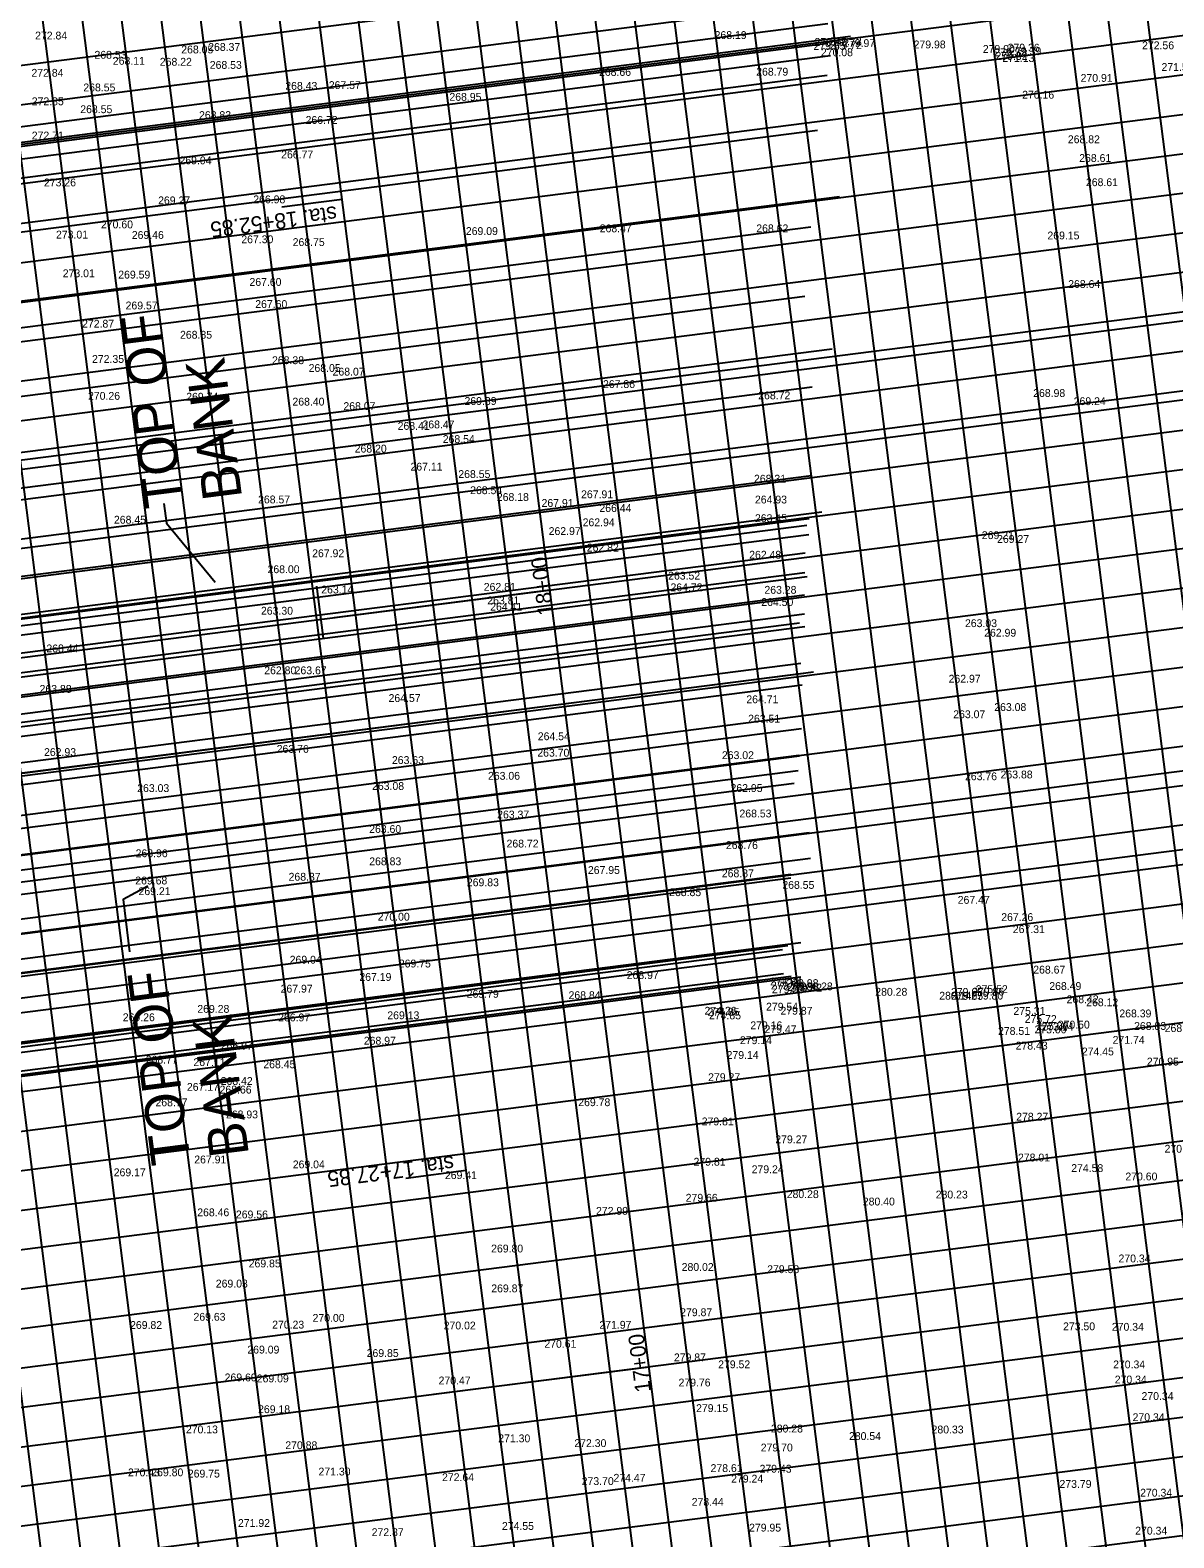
# Model space of a CAD drawing. Extents: x 2166991 to 2168450, y 842134 to 844444.
# Drawn here: x 2167986.8 to 2168132.8, y 843313.8 to 843506.3 of the extents above; entities that cross this region are included whole.
import ezdxf

# ---------------------------------------------------------------- set-up
doc = ezdxf.new("R2010")
doc.units = 0
for name, color, linetype in [('Exist Plan Preparation Drainage Notes Label', 7, 'Continuous'), ('Prop Boundary Buffer Zone 1', 7, 'Continuous'), ('Prop Drainage Structure Pipe Alternate 18in Label', 7, 'Continuous'), ('Prop Drainage Structure Scour Hole Label', 7, 'Continuous'), ('Prop Erosion Rip Rap Class II', 7, 'Continuous'), ('Scratch_Level_3', 7, 'Continuous')]:
    doc.layers.add(name, color=color, linetype=linetype)

msp = doc.modelspace()

# ---------------------------------------------------------------- linework, layer by layer
at = {"layer": 'Exist Plan Preparation Drainage Notes Label'}
for p, q in [((2168181.94, 842821.17), (2168023.56, 844061.1)), ((2168132.34, 842814.84), (2167973.96, 844054.76)), ((2168082.74, 842808.5), (2167924.37, 844048.43)), ((2168208.53, 842849.77), (2168056.49, 844040.1)), ((2168213.49, 842850.4), (2168061.45, 844040.73)), ((2168193.65, 842847.87), (2168041.61, 844038.2)), ((2168198.61, 842848.5), (2168046.57, 844038.83)), ((2168203.57, 842849.14), (2168051.53, 844039.47)), ((2168183.73, 842846.6), (2168031.69, 844036.93)), ((2168188.69, 842847.24), (2168036.65, 844037.57)), ((2168163.89, 842844.07), (2168011.85, 844034.4)), ((2168168.85, 842844.7), (2168016.81, 844035.03)), ((2168173.81, 842845.34), (2168021.77, 844035.67)), ((2168144.05, 842841.54), (2167992.01, 844031.86)), ((2168149.01, 842842.17), (2167996.97, 844032.5)), ((2168153.97, 842842.8), (2168001.93, 844033.13)), ((2168158.93, 842843.44), (2168006.89, 844033.77)), ((2168134.13, 842840.27), (2167982.09, 844030.6)), ((2168139.09, 842840.9), (2167987.05, 844031.23)), ((2168114.29, 842837.73), (2167962.25, 844028.06)), ((2168119.25, 842838.37), (2167967.21, 844028.7)), ((2168124.21, 842839), (2167972.17, 844029.33)), ((2168099.41, 842835.83), (2167947.37, 844026.16)), ((2168104.37, 842836.47), (2167952.33, 844026.8)), ((2168109.33, 842837.1), (2167957.29, 844027.43)), ((2168084.53, 842833.93), (2167932.49, 844024.26)), ((2168089.49, 842834.57), (2167937.45, 844024.9)), ((2168094.45, 842835.2), (2167942.41, 844025.53)), ((2168069.66, 842832.03), (2167917.61, 844022.36)), ((2168074.61, 842832.67), (2167922.57, 844023)), ((2168054.78, 842830.13), (2167902.74, 844020.46)), ((2168059.74, 842830.77), (2167907.69, 844021.1)), ((2168064.7, 842831.4), (2167912.65, 844021.73)), ((2168049.82, 842829.5), (2167897.78, 844019.83)), ((2168142.84, 843521.87), (2167646.87, 843458.52)), ((2168143.48, 843516.91), (2167647.51, 843453.56)), ((2168144.11, 843511.95), (2167648.14, 843448.6)), ((2168144.74, 843506.99), (2167648.77, 843443.64)), ((2168145.38, 843502.03), (2167649.41, 843438.68)), ((2168146.01, 843497.07), (2167625.24, 843430.55)), ((2168146.64, 843492.11), (2167650.67, 843428.76)), ((2168147.28, 843487.15), (2167651.31, 843423.8)), ((2168147.91, 843482.19), (2167651.94, 843418.84)), ((2168148.54, 843477.23), (2167652.57, 843413.88)), ((2168149.18, 843472.27), (2167653.21, 843408.92)), ((2168149.81, 843467.31), (2167653.84, 843403.96)), ((2168150.44, 843462.35), (2167654.47, 843399)), ((2168151.08, 843457.39), (2167655.11, 843394.04)), ((2168151.71, 843452.43), (2167655.74, 843389.08)), ((2168152.35, 843447.47), (2167631.58, 843380.95)), ((2168152.98, 843442.51), (2167657.01, 843379.16)), ((2168153.61, 843437.55), (2167657.64, 843374.2)), ((2168154.25, 843432.59), (2167658.28, 843369.24)), ((2168154.88, 843427.63), (2167658.91, 843364.28)), ((2168155.51, 843422.67), (2167659.54, 843359.32)), ((2168156.15, 843417.71), (2167660.18, 843354.36)), ((2168156.78, 843412.75), (2167660.81, 843349.4)), ((2168157.41, 843407.79), (2167661.44, 843344.44)), ((2168158.05, 843402.83), (2167662.08, 843339.48)), ((2168158.68, 843397.87), (2167637.91, 843331.35)), ((2168159.31, 843392.91), (2167663.34, 843329.56)), ((2168159.95, 843387.95), (2167663.98, 843324.6)), ((2168160.58, 843382.99), (2167664.61, 843319.64)), ((2168161.21, 843378.03), (2167665.24, 843314.68)), ((2168161.85, 843373.07), (2167665.88, 843309.72)), ((2168162.48, 843368.11), (2167666.51, 843304.76)), ((2168163.11, 843363.15), (2167667.14, 843299.8)), ((2168163.75, 843358.2), (2167667.78, 843294.84)), ((2168164.38, 843353.24), (2167668.41, 843289.89)), ((2168165.02, 843348.28), (2167644.25, 843281.76)), ((2168165.65, 843343.32), (2167669.68, 843279.97)), ((2168166.28, 843338.36), (2167670.31, 843275.01)), ((2168166.92, 843333.4), (2167670.95, 843270.05)), ((2168167.55, 843328.44), (2167671.58, 843265.09)), ((2168168.18, 843323.48), (2167672.21, 843260.13)), ((2168168.82, 843318.52), (2167672.85, 843255.17))]:
    msp.add_line(p, q, dxfattribs=at)
at = {"layer": 'Prop Boundary Buffer Zone 1'}
for p, q in [((2168091.54, 843505.51), (2167796.91, 843467.87)), ((2168090.16, 843485.03), (2167799.4, 843447.89)), ((2168089.2, 843465.59), (2167801.33, 843428.82)), ((2168087.87, 843444.75), (2167804.17, 843408.52)), ((2168086.81, 843424.32), (2167806.08, 843388.46)), ((2168086.26, 843403.82), (2167808.5, 843368.34)), ((2168086.42, 843400.54), (2167809.11, 843365.12)), ((2168085.19, 843389.79), (2167809.7, 843354.6)), ((2168085.19, 843385.4), (2167810.15, 843350.27))]:
    msp.add_line(p, q, dxfattribs=at)
at = {"layer": 'Prop Drainage Structure Pipe Alternate 18in Label'}
for p, q in [((2168026.62, 843484.68), (2168018.91, 843483.7)), ((2168053.15, 843434.79), (2168025.6, 843431.27)), ((2168042.46, 843360.69), (2168034.74, 843359.7)), ((2168065.82, 843335.6), (2168038.27, 843332.08))]:
    msp.add_line(p, q, dxfattribs=at)
at = {"layer": 'Prop Drainage Structure Scour Hole Label'}
for p, q in [((2168088.64, 843507.14), (2167815.29, 843472.22)), ((2168088.67, 843504.62), (2167844.97, 843473.49)), ((2168088.99, 843503.04), (2167845.52, 843471.94)), ((2168088.56, 843500.54), (2167849.85, 843470.04)), ((2168087.31, 843493.51), (2167854.58, 843463.78)), ((2168086.48, 843481.16), (2167855.37, 843451.64)), ((2168085.73, 843472.3), (2167855.38, 843442.88)), ((2168086.66, 843460.73), (2167855.42, 843431.19)), ((2168086.56, 843449.42), (2167857.98, 843420.22)), ((2168086.26, 843443.93), (2167870.81, 843416.41)), ((2168085.95, 843443.06), (2167880.74, 843416.85)), ((2168086.24, 843441.89), (2167881.38, 843415.73)), ((2168085.76, 843439.53), (2167887.53, 843414.21)), ((2168085.72, 843437.01), (2167889.23, 843411.91)), ((2168086, 843436.52), (2167889.35, 843411.4)), ((2168085.66, 843434.17), (2167887.75, 843408.89)), ((2168085.67, 843431.76), (2167883.64, 843405.95)), ((2168085.72, 843430.12), (2167878.89, 843403.7)), ((2168085.01, 843430.58), (2167882.49, 843404.72)), ((2168085.22, 843425.45), (2167879.76, 843399.21)), ((2168085.6, 843424.18), (2167882.56, 843398.25)), ((2168085.36, 843422.68), (2167884.87, 843397.07)), ((2168085.27, 843417.09), (2167889.05, 843392.03)), ((2168085.04, 843413.62), (2167890.03, 843388.71)), ((2168084.94, 843413.7), (2167890.46, 843388.86)), ((2168084.37, 843410.11), (2167885.05, 843384.65)), ((2168084.85, 843411.72), (2167889.77, 843386.8)), ((2168083.92, 843398.49), (2167861.36, 843370.07)), ((2168083.92, 843398.03), (2167861.12, 843369.57)), ((2168082.84, 843388.87), (2167838.25, 843357.63)), ((2168083.55, 843389.39), (2167839.68, 843358.24)), ((2168083.95, 843385.46), (2167834.18, 843353.55)), ((2168082.98, 843385.82), (2167834.96, 843354.14))]:
    msp.add_line(p, q, dxfattribs=at)
at = {"layer": 'Prop Erosion Rip Rap Class II'}
msp.add_line((2168024.22, 843428.68), (2168023.37, 843435.3), dxfattribs=at)
for points in [[(2168003.85, 843445.87), (2168004.17, 843443.36), (2168010.37, 843435.83)], [(2168001.8, 843397), (2167998.64, 843395.31), (2167999.43, 843388.63)]]:
    msp.add_lwpolyline(points, dxfattribs=at)
at = {"layer": 'Scratch_Level_3'}
for p, q in [((2167815.39, 843428.51), (2168411.81, 843504.69)), ((2167861.89, 843424.37), (2168413.08, 843494.78)), ((2167871.33, 843378.22), (2168277.38, 843430.09)), ((2167817.84, 843361.31), (2168278.64, 843420.17))]:
    msp.add_line(p, q, dxfattribs=at)

# ---------------------------------------------------------------- texts
at = {"layer": 'Prop Drainage Structure Pipe Alternate 18in Label'}
for s, rotation, p in [('sta. 18+52.85', 187.279, (2168025.82, 843483.86)), ('18+00', 97.279, (2168053.64, 843431.72)), ('sta. 17+27.85', 187.279, (2168040.78, 843362.61)), ('17+00', 97.279, (2168066.06, 843332.5))]:
    msp.add_text(s, height=2, rotation=rotation, dxfattribs=at).set_placement(p)
at = {"layer": 'Prop Erosion Rip Rap Class II'}
for s, p in [('TOP OF', (2168006.4, 843445.69)), ('BANK', (2168013.84, 843446.64)), ('TOP OF', (2168007.27, 843361.78)), ('BANK', (2168014.71, 843362.73))]:
    msp.add_text(s, height=5, rotation=97.279, dxfattribs=at).set_placement(p)
at = {"layer": 'Scratch_Level_3'}
for s, p in [('272.84', (2167987.39, 843505.13)), ('268.05', (2168006.06, 843503.35)), ('268.37', (2168009.5, 843503.67)), ('268.19', (2168074.19, 843505.19)), ('279.55', (2168086.82, 843503.8)), ('279.47', (2168086.95, 843504.31)), ('279.72', (2168088.89, 843504.4)), ('279.72', (2168088.91, 843503.9)), ('279.97', (2168090.6, 843504.16)), ('279.98', (2168099.61, 843503.99)), ('279.90', (2168108.45, 843503.42)), ('279.36', (2168111.62, 843503.58)), ('272.56', (2168128.79, 843503.88)), ('268.53', (2167994.97, 843502.67)), ('268.11', (2167997.32, 843501.9)), ('268.22', (2168003.32, 843501.78)), ('270.08', (2168087.77, 843502.99)), ('279.32', (2168109.9, 843502.99)), ('279.32', (2168110.06, 843502.52)), ('271.13', (2168110.94, 843502.25)), ('279.39', (2168111.83, 843503.13)), ('272.84', (2167986.92, 843500.37)), ('268.53', (2168009.7, 843501.38)), ('268.66', (2168059.42, 843500.48)), ('268.79', (2168079.5, 843500.51)), ('270.91', (2168120.94, 843499.72)), ('271.57', (2168131.27, 843501.11)), ('268.55', (2167993.55, 843498.5)), ('268.43', (2168019.35, 843498.7)), ('267.57', (2168024.9, 843498.8)), ('270.16', (2168113.47, 843497.57)), ('272.85', (2167986.96, 843496.73)), ('268.55', (2167993.16, 843495.72)), ('268.95', (2168040.31, 843497.3)), ('268.83', (2168008.33, 843494.97)), ('266.72', (2168021.94, 843494.35)), ('272.71', (2167986.96, 843492.36)), ('268.82', (2168119.31, 843491.88)), ('266.77', (2168018.82, 843489.94)), ('269.04', (2168005.83, 843489.19)), ('268.61', (2168120.76, 843489.49)), ('273.26', (2167988.52, 843486.37)), ('268.61', (2168121.62, 843486.4)), ('269.27', (2168003.1, 843484.08)), ('266.98', (2168015.26, 843484.21)), ('270.60', (2167995.8, 843481.01)), ('268.47', (2168059.51, 843480.51)), ('268.62', (2168079.51, 843480.51)), ('273.01', (2167990.06, 843479.71)), ('269.46', (2167999.74, 843479.66)), ('267.30', (2168013.73, 843479.11)), ('268.75', (2168020.29, 843478.75)), ('269.09', (2168042.41, 843480.16)), ('269.15', (2168116.7, 843479.6)), ('273.01', (2167990.92, 843474.77)), ('269.59', (2167998.01, 843474.6)), ('267.60', (2168014.77, 843473.66)), ('268.64', (2168119.35, 843473.4)), ('269.57', (2167998.95, 843470.66)), ('267.60', (2168015.51, 843470.84)), ('272.87', (2167993.39, 843468.33)), ('268.85', (2168005.9, 843466.92)), ('272.35', (2167994.66, 843463.83)), ('268.38', (2168017.65, 843463.67)), ('268.05', (2168022.33, 843462.68)), ('268.07', (2168025.39, 843462.21)), ('270.26', (2167994.15, 843459.12)), ('267.86', (2168059.93, 843460.62)), ('268.72', (2168079.76, 843459.18)), ('268.98', (2168114.88, 843459.48)), ('269.74', (2168006.69, 843459.01)), ('268.40', (2168020.26, 843458.38)), ('268.07', (2168026.77, 843457.81)), ('269.39', (2168042.24, 843458.46)), ('269.24', (2168120.06, 843458.44)), ('268.41', (2168033.7, 843455.28)), ('268.47', (2168036.87, 843455.47)), ('268.54', (2168039.46, 843453.6)), ('268.20', (2168028.21, 843452.38)), ('267.11', (2168035.34, 843450.08)), ('268.55', (2168041.45, 843449.13)), ('268.31', (2168079.22, 843448.54)), ('268.57', (2168015.87, 843445.89)), ('268.54', (2168042.96, 843447.07)), ('268.18', (2168046.37, 843446.2)), ('267.91', (2168057.13, 843446.55)), ('264.93', (2168079.34, 843445.88)), ('267.91', (2168052.08, 843445.44)), ('266.44', (2168059.47, 843444.79)), ('268.45', (2167997.46, 843443.3)), ('262.97', (2168052.99, 843441.85)), ('262.94', (2168057.33, 843442.97)), ('263.45', (2168079.34, 843443.5)), ('269.21', (2168108.32, 843441.33)), ('269.27', (2168110.27, 843440.84)), ('267.92', (2168022.78, 843439.02)), ('262.82', (2168057.86, 843439.74)), ('262.48', (2168078.6, 843438.83)), ('268.00', (2168017.08, 843436.98)), ('263.52', (2168068.25, 843436.16)), ('263.14', (2168023.94, 843434.39)), ('262.81', (2168044.7, 843434.73)), ('264.72', (2168068.55, 843434.67)), ('263.28', (2168080.55, 843434.35)), ('263.81', (2168045.15, 843433)), ('264.41', (2168045.52, 843432.19)), ('264.50', (2168080.15, 843432.79)), ('263.30', (2168016.24, 843431.68)), ('263.03', (2168106.17, 843430.09)), ('262.99', (2168108.62, 843428.87)), ('268.44', (2167988.83, 843426.87)), ('262.80', (2168016.66, 843424.07)), ('263.67', (2168020.54, 843424.07)), ('262.97', (2168104.08, 843423)), ('263.88', (2167987.96, 843421.7)), ('264.57', (2168032.54, 843420.53)), ('264.71', (2168078.24, 843420.37)), ('263.08', (2168109.91, 843419.38)), ('263.51', (2168078.47, 843417.9)), ('263.07', (2168104.67, 843418.46)), ('264.54', (2168051.6, 843415.65)), ('262.93', (2167988.53, 843413.63)), ('263.76', (2168018.25, 843414.04)), ('263.70', (2168051.54, 843413.55)), ('263.02', (2168075.12, 843413.24)), ('263.63', (2168032.97, 843412.61)), ('263.03', (2168000.43, 843409.03)), ('263.08', (2168030.43, 843409.3)), ('263.06', (2168045.24, 843410.6)), ('262.95', (2168076.22, 843409.04)), ('263.76', (2168106.17, 843410.54)), ('263.88', (2168110.72, 843410.77)), ('263.37', (2168046.41, 843405.66)), ('268.53', (2168077.36, 843405.79)), ('263.60', (2168030.06, 843403.81)), ('268.72', (2168047.61, 843401.95)), ('268.76', (2168075.63, 843401.75)), ('263.96', (2168000.23, 843400.71)), ('268.83', (2168030.07, 843399.68)), ('268.37', (2168019.77, 843397.71)), ('267.95', (2168058, 843398.57)), ('268.87', (2168075.11, 843398.15)), ('269.68', (2168000.18, 843397.23)), ('269.21', (2168000.6, 843395.87)), ('269.83', (2168042.54, 843397)), ('268.85', (2168068.38, 843395.74)), ('268.55', (2168082.84, 843396.67)), ('267.47', (2168105.24, 843394.76)), ('270.00', (2168031.15, 843392.61)), ('267.26', (2168110.8, 843392.56)), ('267.31', (2168112.28, 843391.02)), ('269.04', (2168019.91, 843387.12)), ('269.75', (2168033.85, 843386.63)), ('267.19', (2168028.81, 843384.92)), ('268.97', (2168062.96, 843385.15)), ('274.84', (2168081.27, 843384.34)), ('279.98', (2168083.37, 843384.13)), ('268.67', (2168114.89, 843385.85)), ('267.97', (2168018.75, 843383.42)), ('269.79', (2168042.52, 843382.76)), ('268.84', (2168055.53, 843382.59)), ('279.56', (2168081.38, 843383.83)), ('279.53', (2168081.51, 843383.34)), ('279.98', (2168083.44, 843383.64)), ('279.82', (2168083.82, 843383.55)), ('280.28', (2168085.18, 843383.71)), ('280.28', (2168094.71, 843383.02)), ('280.14', (2168102.88, 843382.52)), ('279.65', (2168104.38, 843383)), ('279.65', (2168104.39, 843382.5)), ('279.80', (2168106.96, 843382.53)), ('279.86', (2168107.08, 843383.04)), ('275.52', (2168107.54, 843383.36)), ('268.49', (2168116.94, 843383.76)), ('268.42', (2168119.15, 843382.07)), ('269.28', (2168008.11, 843380.84)), ('274.26', (2168072.9, 843380.6)), ('274.85', (2168073.27, 843380.47)), ('279.54', (2168080.76, 843381.12)), ('279.87', (2168082.6, 843380.6)), ('275.31', (2168112.36, 843380.58)), ('268.12', (2168121.65, 843381.68)), ('268.39', (2168125.89, 843380.26)), ('269.26', (2167998.59, 843379.77)), ('266.97', (2168018.43, 843379.75)), ('269.13', (2168032.38, 843380.02)), ('274.85', (2168073.47, 843380.01)), ('279.16', (2168078.75, 843378.74)), ('279.47', (2168080.56, 843378.24)), ('275.72', (2168113.8, 843379.55)), ('275.00', (2168115.05, 843378.22)), ('275.00', (2168115.28, 843378.66)), ('273.14', (2168115.94, 843378.57)), ('270.50', (2168118.02, 843378.83)), ('268.83', (2168127.77, 843378.66)), ('268.42', (2168131.68, 843378.38)), ('268.97', (2168029.38, 843376.78)), ('279.14', (2168077.42, 843376.84)), ('278.51', (2168110.39, 843378.02)), ('271.74', (2168125.03, 843376.88)), ('268.77', (2168001.52, 843374.36)), ('266.97', (2168011.1, 843376.15)), ('279.14', (2168075.72, 843374.95)), ('278.43', (2168112.64, 843376.15)), ('274.45', (2168121.1, 843375.4)), ('267.11', (2168007.61, 843374.04)), ('268.45', (2168016.54, 843373.76)), ('270.95', (2168129.4, 843374.11)), ('267.17', (2168006.78, 843370.88)), ('268.66', (2168010.95, 843370.53)), ('268.42', (2168011.09, 843371.63)), ('279.27', (2168073.36, 843372.12)), ('268.77', (2168002.76, 843368.9)), ('269.78', (2168056.77, 843368.92)), ('268.93', (2168011.77, 843367.36)), ('278.27', (2168112.71, 843367.07)), ('279.81', (2168072.54, 843366.47)), ('279.27', (2168081.94, 843364.18)), ('270.02', (2168131.66, 843362.98)), ('267.91', (2168007.72, 843361.61)), ('269.04', (2168020.3, 843360.98)), ('279.81', (2168071.5, 843361.32)), ('278.01', (2168112.94, 843361.86)), ('269.17', (2167997.43, 843359.97)), ('269.41', (2168039.74, 843359.61)), ('279.24', (2168078.92, 843360.36)), ('274.58', (2168119.74, 843360.51)), ('270.60', (2168126.66, 843359.44)), ('280.28', (2168083.4, 843357.18)), ('280.23', (2168102.43, 843357.13)), ('279.66', (2168070.49, 843356.72)), ('280.40', (2168093.12, 843356.24)), ('268.46', (2168008.1, 843354.86)), ('269.56', (2168013.04, 843354.59)), ('272.99', (2168059.04, 843355.05)), ('269.80', (2168045.64, 843350.24)), ('269.85', (2168014.67, 843348.33)), ('280.02', (2168069.98, 843347.88)), ('279.58', (2168080.9, 843347.6)), ('270.34', (2168125.78, 843348.97)), ('269.03', (2168010.47, 843345.76)), ('269.87', (2168045.66, 843345.15)), ('279.87', (2168069.79, 843342.1)), ('269.82', (2167999.52, 843340.47)), ('269.63', (2168007.62, 843341.52)), ('270.23', (2168017.67, 843340.52)), ('270.00', (2168022.83, 843341.38)), ('270.02', (2168039.58, 843340.41)), ('271.97', (2168059.47, 843340.5)), ('273.50', (2168118.7, 843340.3)), ('270.34', (2168124.93, 843340.24)), ('270.61', (2168052.44, 843338.07)), ('269.09', (2168014.5, 843337.33)), ('269.85', (2168029.74, 843336.89)), ('279.87', (2168068.99, 843336.34)), ('279.52', (2168074.64, 843335.45)), ('270.34', (2168125.09, 843335.44)), ('269.60', (2168011.6, 843333.78)), ('269.09', (2168015.7, 843333.65)), ('270.47', (2168038.93, 843333.39)), ('279.76', (2168069.58, 843333.13)), ('270.34', (2168125.3, 843333.51)), ('270.34', (2168128.72, 843331.4)), ('269.18', (2168015.87, 843329.72)), ('279.15', (2168071.82, 843329.86)), ('270.34', (2168127.58, 843328.7)), ('270.13', (2168006.65, 843327.14)), ('280.28', (2168081.38, 843327.25)), ('280.54', (2168091.35, 843326.29)), ('280.33', (2168101.9, 843327.13)), ('270.88', (2168019.35, 843325.12)), ('271.30', (2168046.55, 843326)), ('272.30', (2168056.27, 843325.39)), ('279.70', (2168080.08, 843324.83)), ('270.43', (2167999.25, 843321.65)), ('269.80', (2168002.23, 843321.66)), ('269.75', (2168006.9, 843321.5)), ('271.30', (2168023.59, 843321.76)), ('272.64', (2168039.37, 843321.04)), ('273.70', (2168057.21, 843320.54)), ('274.47', (2168061.27, 843320.96)), ('278.61', (2168073.67, 843322.2)), ('279.24', (2168076.3, 843320.85)), ('279.43', (2168079.93, 843322.12)), ('273.79', (2168118.24, 843320.18)), ('270.34', (2168128.54, 843319.06)), ('278.44', (2168071.26, 843317.89)), ('271.92', (2168013.3, 843315.19)), ('274.55', (2168047.02, 843314.81)), ('272.87', (2168030.38, 843314.02)), ('279.95', (2168078.59, 843314.6)), ('270.34', (2168127.91, 843314.21))]:
    msp.add_text(s, height=1, dxfattribs=at).set_placement(p)

doc.saveas('drawing.dxf')
